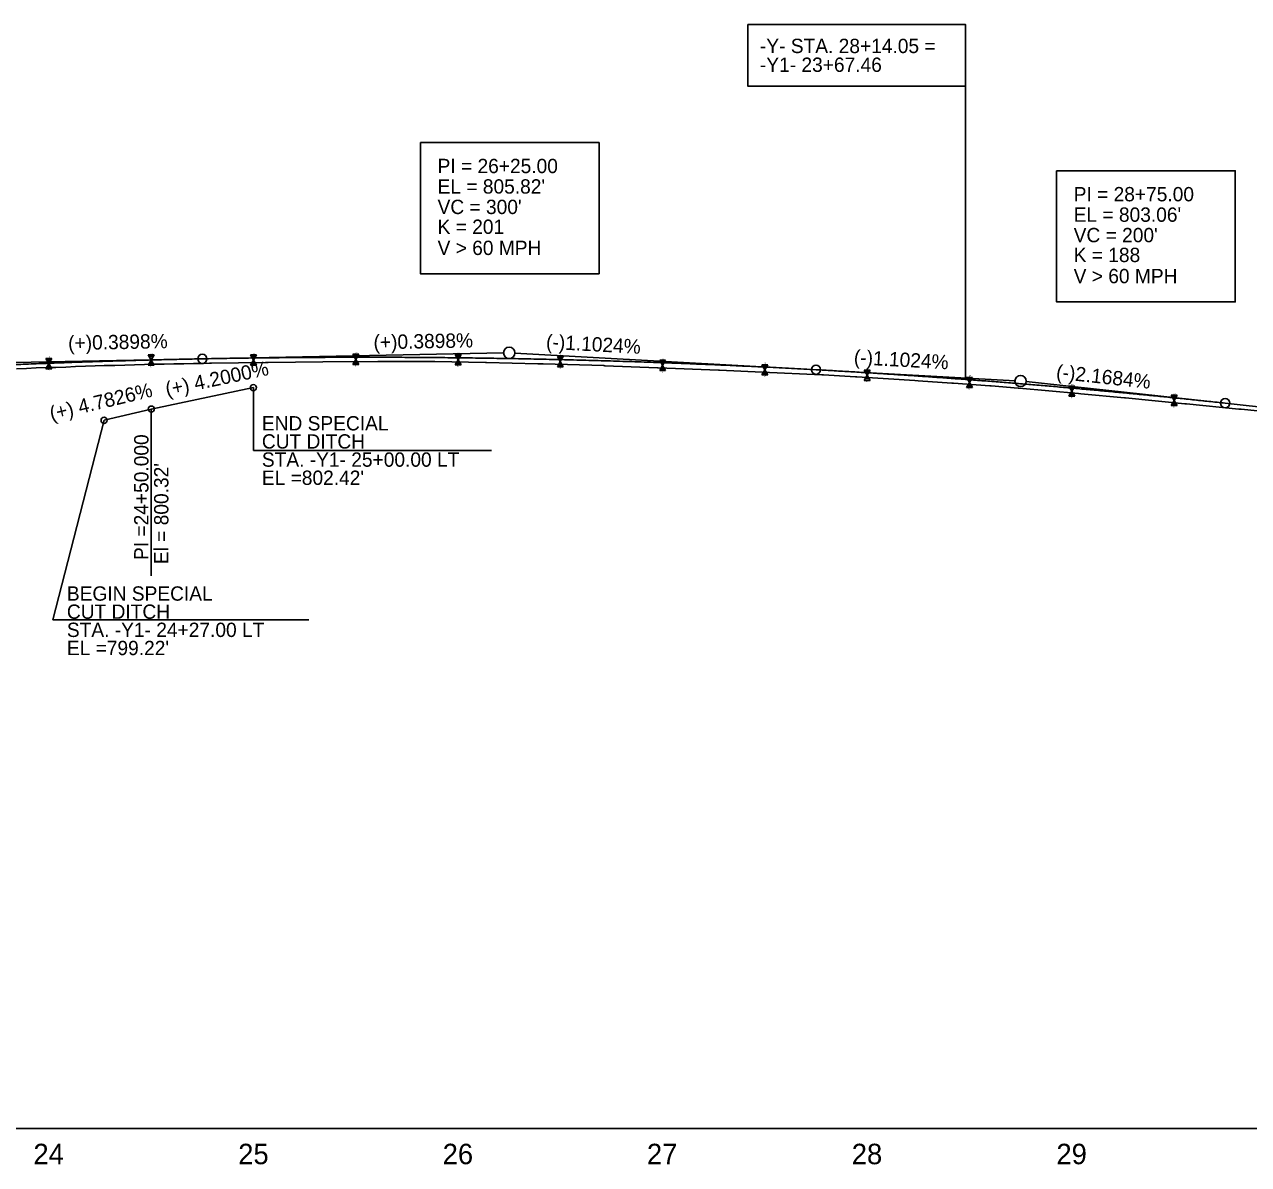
# Model space of a CAD drawing. Extents: x 579185 to 595036, y -53221 to -44640.
# Drawn here: x 580710 to 581308, y -48575 to -48018 of the extents above; entities that cross this region are included whole.
import ezdxf

# ---------------------------------------------------------------- set-up
doc = ezdxf.new("R2010")
doc.units = 0
for name, color, linetype in [('Exist Profile Cell', 7, 'Continuous'), ('Exist Vertical Profile Ground Line', 7, 'Continuous'), ('Exist Vertical Profile Horizontal Axis Label Major', 7, 'Continuous'), ('Old_Level_2', 7, 'Continuous'), ('Prop Grid Mask', 7, 'Continuous'), ('Prop Vertical Profile Curve Label', 7, 'Continuous'), ('Prop Vertical Profile Ditch Grade Left', 7, 'Continuous'), ('Prop Vertical Profile Ditch Grade Left Label', 7, 'Continuous'), ('Prop Vertical Profile Grade', 7, 'Continuous'), ('Prop Vertical Profile Grade Label', 7, 'Continuous'), ('Prop VPI Ditch Grade Left Label', 7, 'Continuous'), ('Prop VPI Label', 7, 'Continuous')]:
    doc.layers.add(name, color=color, linetype=linetype)

msp = doc.modelspace()

# ---------------------------------------------------------------- linework, layer by layer
at = {"layer": 'Exist Profile Cell'}
msp.add_line((579321.48, -48557.09), (581829.78, -48557.09), dxfattribs=at)
at = {"layer": 'Exist Vertical Profile Ground Line'}
msp.add_lwpolyline([(580705.7, -48185.81), (580710.5, -48185.61), (580715.31, -48185.41), (580720.12, -48185.22), (580720.51, -48185.2), (580722.07, -48185.17), (580724.16, -48185.13), (580724.92, -48185.1), (580729.73, -48184.93), (580734.54, -48184.75), (580739.35, -48184.58), (580744.15, -48184.41), (580748.52, -48184.26), (580748.96, -48184.25), (580750.36, -48184.23), (580753.77, -48184.13), (580758.58, -48184), (580763.38, -48183.87), (580768.19, -48183.74), (580773, -48183.61), (580774.2, -48183.57), (580775.56, -48183.55), (580777.8, -48183.51), (580782.61, -48183.42), (580787.42, -48183.33), (580792.23, -48183.24), (580797.03, -48183.15), (580799.93, -48183.1), (580800.89, -48183.08), (580827.28, -48182.75), (580827.95, -48182.75), (580828.6, -48182.74), (580855.37, -48182.48), (580882.3, -48182.16), (580882.67, -48182.16), (580883, -48182.16), (580909.82, -48182.25), (580910.21, -48182.26), (580934.93, -48182.78), (580935.33, -48182.8), (580960.5, -48183.33), (580962.75, -48183.4), (580963.06, -48183.41), (580992.75, -48184.26), (580993.18, -48184.28), (581018.94, -48185.27), (581019.32, -48185.28), (581048.77, -48186.42), (581049.24, -48186.44), (581070.14, -48187.41), (581099.34, -48188.77), (581100.14, -48188.82), (581115.84, -48189.78), (581116.34, -48189.81), (581144.82, -48191.56), (581146.35, -48191.64), (581162.93, -48192.83), (581163.62, -48192.89), (581181.47, -48194.08), (581182.03, -48194.13), (581195.27, -48195.28), (581195.7, -48195.32), (581224.81, -48197.85), (581225.9, -48197.96), (581247.31, -48200.03), (581247.79, -48200.07), (581276.68, -48202.87), (581277.55, -48202.95), (581303.18, -48205.5), (581304.3, -48205.61), (581333.03, -48208.47)], dxfattribs=at)
at = {"layer": 'Old_Level_2'}
for p, q in [((580721.48, -48183.25), (580720.04, -48180.75)), ((580720.04, -48180.75), (580722.93, -48180.75)), ((580720.04, -48185.75), (580721.48, -48183.25)), ((580720.52, -48181.58), (580722.45, -48181.58)), ((580721, -48182.41), (580721.97, -48182.41)), ((580721, -48184.08), (580721.96, -48184.08)), ((580721.48, -48183.25), (580722.93, -48180.75)), ((580722.93, -48185.75), (580721.48, -48183.25)), ((580771.48, -48181.53), (580770.04, -48179.03)), ((580770.04, -48179.03), (580772.93, -48179.03)), ((580770.04, -48184.03), (580771.48, -48181.53)), ((580770.04, -48184.03), (580772.93, -48184.03)), ((580770.52, -48179.86), (580772.45, -48179.86)), ((580770.52, -48183.19), (580772.45, -48183.19)), ((580771, -48180.69), (580771.97, -48180.69)), ((580771, -48182.36), (580771.96, -48182.36)), ((580771.48, -48181.53), (580772.93, -48179.03)), ((580772.93, -48184.03), (580771.48, -48181.53)), ((580821.48, -48181.51), (580820.04, -48179.01)), ((580820.04, -48179.01), (580822.93, -48179.01)), ((580820.04, -48184.01), (580821.48, -48181.51)), ((580820.04, -48184.01), (580822.93, -48184.01)), ((580820.52, -48179.84), (580822.45, -48179.84)), ((580820.52, -48183.18), (580822.45, -48183.18)), ((580821, -48180.68), (580821.97, -48180.68)), ((580821, -48182.35), (580821.96, -48182.35)), ((580821.48, -48181.51), (580822.93, -48179.01)), ((580822.93, -48184.01), (580821.48, -48181.51)), ((580871.48, -48181.2), (580870.04, -48178.7)), ((580870.04, -48178.7), (580872.93, -48178.7)), ((580870.04, -48183.7), (580871.48, -48181.2)), ((580870.04, -48183.7), (580872.93, -48183.7)), ((580870.52, -48179.53), (580872.45, -48179.53)), ((580870.52, -48182.87), (580872.45, -48182.87)), ((580871, -48180.37), (580871.97, -48180.37)), ((580871, -48182.04), (580871.96, -48182.04)), ((580871.48, -48181.2), (580872.93, -48178.7)), ((580872.93, -48183.7), (580871.48, -48181.2)), ((580921.48, -48181.34), (580920.04, -48178.84)), ((580920.04, -48178.84), (580922.93, -48178.84)), ((580920.04, -48183.84), (580921.48, -48181.34)), ((580920.04, -48183.84), (580922.93, -48183.84)), ((580920.52, -48179.67), (580922.45, -48179.67)), ((580920.52, -48183.01), (580922.45, -48183.01)), ((580921, -48180.51), (580921.97, -48180.51)), ((580921, -48182.18), (580921.96, -48182.18)), ((580921.48, -48181.34), (580922.93, -48178.84)), ((580922.93, -48183.84), (580921.48, -48181.34)), ((580971.48, -48182.31), (580970.04, -48179.81)), ((580970.04, -48179.81), (580972.93, -48179.81)), ((580970.04, -48184.81), (580971.48, -48182.31)), ((580970.52, -48180.64), (580972.45, -48180.64)), ((580970.52, -48183.98), (580972.45, -48183.98)), ((580971, -48181.48), (580971.97, -48181.48)), ((580971, -48183.15), (580971.96, -48183.15)), ((580971.48, -48182.31), (580972.93, -48179.81)), ((580972.93, -48184.81), (580971.48, -48182.31)), ((581021.48, -48184.14), (581020.04, -48181.64)), ((581020.04, -48181.64), (581022.93, -48181.64)), ((581020.04, -48186.64), (581021.48, -48184.14)), ((581020.52, -48182.47), (581022.45, -48182.47)), ((581021, -48183.3), (581021.97, -48183.3)), ((581021.48, -48184.14), (581022.93, -48181.64)), ((581022.93, -48186.64), (581021.48, -48184.14)), ((581071.48, -48186.31), (581070.04, -48183.81)), ((581070.04, -48183.81), (581072.93, -48183.81)), ((581071.48, -48186.31), (581072.93, -48183.81)), ((580720.04, -48185.75), (580722.93, -48185.75)), ((580720.52, -48184.91), (580722.45, -48184.91)), ((580970.04, -48184.81), (580972.93, -48184.81)), ((581020.04, -48186.64), (581022.93, -48186.64)), ((581020.52, -48185.8), (581022.45, -48185.8)), ((581021, -48184.97), (581021.96, -48184.97)), ((581070.04, -48188.81), (581071.48, -48186.31)), ((581070.04, -48188.81), (581072.93, -48188.81)), ((581070.52, -48184.64), (581072.45, -48184.64)), ((581070.52, -48187.97), (581072.45, -48187.97)), ((581071, -48185.47), (581071.97, -48185.47)), ((581071, -48187.14), (581071.96, -48187.14)), ((581072.93, -48188.81), (581071.48, -48186.31)), ((581121.48, -48188.95), (581120.04, -48186.45)), ((581120.04, -48186.45), (581122.93, -48186.45)), ((581120.04, -48191.45), (581121.48, -48188.95)), ((581120.52, -48187.28), (581122.45, -48187.28)), ((581121, -48188.11), (581121.97, -48188.11)), ((581121, -48189.78), (581121.96, -48189.78)), ((581121.48, -48188.95), (581122.93, -48186.45)), ((581122.93, -48191.45), (581121.48, -48188.95)), ((581171.48, -48192.48), (581170.04, -48189.98)), ((581170.04, -48189.98), (581172.93, -48189.98)), ((581171.48, -48192.48), (581172.93, -48189.98)), ((581120.04, -48191.45), (581122.93, -48191.45)), ((581120.52, -48190.61), (581122.45, -48190.61)), ((581170.04, -48194.98), (581171.48, -48192.48)), ((581170.04, -48194.98), (581172.93, -48194.98)), ((581170.52, -48190.81), (581172.45, -48190.81)), ((581170.52, -48194.14), (581172.45, -48194.14)), ((581171, -48191.64), (581171.97, -48191.64)), ((581171, -48193.31), (581171.96, -48193.31)), ((581172.93, -48194.98), (581171.48, -48192.48)), ((581221.48, -48196.74), (581220.04, -48194.24)), ((581220.04, -48194.24), (581222.93, -48194.24)), ((581220.52, -48195.07), (581222.45, -48195.07)), ((581221, -48195.9), (581221.97, -48195.9)), ((581221.48, -48196.74), (581222.93, -48194.24)), ((581220.04, -48199.24), (581221.48, -48196.74)), ((581220.04, -48199.24), (581222.93, -48199.24)), ((581220.52, -48198.4), (581222.45, -48198.4)), ((581221, -48197.57), (581221.96, -48197.57)), ((581222.93, -48199.24), (581221.48, -48196.74)), ((581271.48, -48201.25), (581270.04, -48198.75)), ((581270.04, -48198.75), (581272.93, -48198.75)), ((581270.04, -48203.75), (581271.48, -48201.25)), ((581270.52, -48199.58), (581272.45, -48199.58)), ((581271, -48200.42), (581271.97, -48200.42)), ((581271, -48202.09), (581271.96, -48202.09)), ((581271.48, -48201.25), (581272.93, -48198.75)), ((581272.93, -48203.75), (581271.48, -48201.25)), ((581270.04, -48203.75), (581272.93, -48203.75)), ((581270.52, -48202.92), (581272.45, -48202.92))]:
    msp.add_line(p, q, dxfattribs=at)
at = {"layer": 'Prop Grid Mask'}
for points in [[(581063.21, -48017.51), (581169.53, -48017.51), (581169.53, -48047.7), (581063.21, -48047.7)], [(580903.09, -48075.2), (580990.45, -48075.2), (580990.45, -48139.37), (580903.09, -48139.37)], [(581214.03, -48088.98), (581301.39, -48088.98), (581301.39, -48153.15), (581214.03, -48153.15)]]:
    msp.add_lwpolyline(points, close=True, dxfattribs=at)
at = {"layer": 'Prop Vertical Profile Curve Label'}
msp.add_line((581169.53, -48191), (581169.53, -48047.7), dxfattribs=at)
for centre in [(580796.48, -48180.92), (580796.48, -48180.92), (581096.48, -48186.26), (581096.48, -48186.26), (581296.48, -48202.62)]:
    msp.add_circle(centre, 2.25, dxfattribs=at)
at = {"layer": 'Prop Vertical Profile Ditch Grade Left'}
msp.add_lwpolyline([(580748.48, -48210.99), (580771.48, -48205.49), (580821.48, -48194.99)], dxfattribs=at)
at = {"layer": 'Prop Vertical Profile Ditch Grade Left Label'}
for p, q in [((580821.48, -48225.74), (580821.48, -48194.99)), ((580771.48, -48287.05), (580771.48, -48205.49)), ((580723.33, -48308.58), (580748.48, -48210.99)), ((580821.48, -48225.74), (580937.78, -48225.74)), ((580723.33, -48308.58), (580848.52, -48308.58))]:
    msp.add_line(p, q, dxfattribs=at)
for centre in [(580821.48, -48194.99), (580771.48, -48205.49), (580748.48, -48210.99)]:
    msp.add_circle(centre, 1.5, dxfattribs=at)
at = {"layer": 'Prop Vertical Profile Grade'}
msp.add_line((581296.48, -48202.62), (581546.48, -48229.72), dxfattribs=at)
for points in [[(580546.48, -48193.64), (580551.48, -48193.23), (580556.48, -48192.83), (580561.48, -48192.43), (580566.48, -48192.04), (580571.48, -48191.66), (580576.48, -48191.28), (580581.48, -48190.91), (580586.48, -48190.55), (580591.48, -48190.19), (580596.48, -48189.84), (580601.48, -48189.49), (580606.48, -48189.15), (580611.48, -48188.82), (580616.48, -48188.5), (580621.48, -48188.17), (580626.48, -48187.86), (580631.48, -48187.55), (580636.48, -48187.25), (580641.48, -48186.96), (580646.48, -48186.67), (580651.48, -48186.38), (580656.48, -48186.11), (580661.48, -48185.84), (580666.48, -48185.57), (580671.48, -48185.32), (580676.48, -48185.07), (580681.48, -48184.82), (580686.48, -48184.58), (580691.48, -48184.35), (580696.48, -48184.12), (580701.48, -48183.9), (580706.48, -48183.69), (580711.48, -48183.48), (580716.48, -48183.28), (580721.48, -48183.09), (580726.48, -48182.9), (580731.48, -48182.72), (580736.48, -48182.54), (580741.48, -48182.37), (580746.48, -48182.21), (580751.48, -48182.05), (580756.48, -48181.9), (580761.48, -48181.76), (580766.48, -48181.62), (580771.48, -48181.48), (580776.48, -48181.36), (580781.48, -48181.24), (580786.48, -48181.13), (580791.48, -48181.02), (580796.48, -48180.92)], [(580796.48, -48180.92), (580802.48, -48180.81), (580808.48, -48180.7), (580814.48, -48180.61), (580820.48, -48180.52), (580826.48, -48180.45), (580832.48, -48180.38), (580838.48, -48180.32), (580844.48, -48180.27), (580850.48, -48180.23), (580856.48, -48180.2), (580862.48, -48180.17), (580868.48, -48180.16), (580874.48, -48180.16), (580880.48, -48180.16), (580886.48, -48180.17), (580892.48, -48180.19), (580898.48, -48180.22), (580904.48, -48180.26), (580910.48, -48180.31), (580916.48, -48180.37), (580922.48, -48180.44), (580928.48, -48180.51), (580934.48, -48180.6), (580940.48, -48180.69), (580946.48, -48180.79), (580952.48, -48180.9), (580958.48, -48181.03), (580964.48, -48181.15), (580970.48, -48181.29), (580976.48, -48181.44), (580982.48, -48181.6), (580988.48, -48181.76), (580994.48, -48181.94), (581000.48, -48182.12), (581006.48, -48182.31), (581012.48, -48182.51), (581018.48, -48182.72), (581024.48, -48182.94), (581030.48, -48183.17), (581036.48, -48183.4), (581042.48, -48183.65), (581048.48, -48183.9), (581054.48, -48184.17), (581060.48, -48184.44), (581066.48, -48184.72), (581072.48, -48185.01), (581078.48, -48185.31), (581084.48, -48185.62), (581090.48, -48185.94), (581096.48, -48186.26)], [(581096.48, -48186.26), (581100.48, -48186.49), (581104.48, -48186.71), (581108.48, -48186.94), (581112.48, -48187.18), (581116.48, -48187.42), (581120.48, -48187.66), (581124.48, -48187.91), (581128.48, -48188.16), (581132.48, -48188.42), (581136.48, -48188.68), (581140.48, -48188.95), (581144.48, -48189.22), (581148.48, -48189.49), (581152.48, -48189.77), (581156.48, -48190.05), (581160.48, -48190.34), (581164.48, -48190.63), (581168.48, -48190.92), (581172.48, -48191.22), (581176.48, -48191.53), (581180.48, -48191.83), (581184.48, -48192.15), (581188.48, -48192.46), (581192.48, -48192.78), (581196.48, -48193.11), (581200.48, -48193.44), (581204.48, -48193.77), (581208.48, -48194.11), (581212.48, -48194.45), (581216.48, -48194.8), (581220.48, -48195.15), (581224.48, -48195.5), (581228.48, -48195.86), (581232.48, -48196.22), (581236.48, -48196.59), (581240.48, -48196.96), (581244.48, -48197.34), (581248.48, -48197.72), (581252.48, -48198.11), (581256.48, -48198.49), (581260.48, -48198.89), (581264.48, -48199.28), (581268.48, -48199.69), (581272.48, -48200.09), (581276.48, -48200.5), (581280.48, -48200.92), (581284.48, -48201.34), (581288.48, -48201.76), (581292.48, -48202.19), (581296.48, -48202.62)]]:
    msp.add_spline(points, degree=3, dxfattribs=at)
at = {"layer": 'Prop VPI Label'}
for p, q in [((580796.48, -48180.92), (580943.73, -48178.05)), ((581096.48, -48186.26), (580949.23, -48178.15)), ((580796.48, -48180.92), (580674.23, -48183.3)), ((581096.48, -48186.26), (581193.74, -48191.62)), ((581296.48, -48202.62), (581199.22, -48192.07))]:
    msp.add_line(p, q, dxfattribs=at)
for centre in [(580946.48, -48178), (581196.48, -48191.78)]:
    msp.add_circle(centre, 2.75, dxfattribs=at)

# ---------------------------------------------------------------- texts
at = {"layer": 'Exist Vertical Profile Horizontal Axis Label Major'}
for s, p in [('24', (580713.93, -48574.59)), ('25', (580814.03, -48574.59)), ('26', (580913.97, -48574.59)), ('27', (581013.82, -48574.59)), ('28', (581113.95, -48574.59)), ('29', (581213.99, -48574.59))]:
    msp.add_text(s, height=10, dxfattribs=at).set_placement(p)
at = {"layer": 'Old_Level_2'}
for p in [(580771.25, -48178.87), (580821.25, -48178.85), (580871.25, -48178.54), (580921.25, -48178.68), (580721.25, -48180.59), (580771.06, -48185.03), (580821.06, -48185.02), (580871.06, -48184.71), (580921.06, -48184.85), (580971.25, -48179.65), (581021.25, -48181.48), (581071.25, -48183.65), (580721.06, -48186.75), (580971.06, -48185.82), (581021.06, -48187.64), (581071.06, -48189.81), (581121.25, -48186.29), (581171.25, -48189.82), (581121.06, -48192.45), (581171.06, -48195.98), (581221.25, -48194.08), (581221.06, -48200.24), (581271.25, -48198.59), (581271.06, -48204.76)]:
    msp.add_text('6"', height=0.8, dxfattribs=at).set_placement(p)
at = {"layer": 'Prop Vertical Profile Curve Label'}
for s, p in [("VC = 300'", (580911.48, -48110.17)), ('K = 201', (580911.48, -48119.86)), ("VC = 200'", (581222.42, -48123.95)), ('V > 60 MPH', (580911.48, -48130.19)), ('K = 188', (581222.42, -48133.64)), ('V > 60 MPH', (581222.42, -48143.97))]:
    msp.add_text(s, height=7, dxfattribs=at).set_placement(p)
at = {"layer": 'Prop Vertical Profile Ditch Grade Left Label'}
for s, rotation, p in [('(+) 4.2000%', 11.85978, (580779.23, -48199.3)), ('(+) 4.7826%', 13.44862, (580722.78, -48211.21))]:
    msp.add_text(s, height=7, rotation=rotation, dxfattribs=at).set_placement(p)
for s, p in [('END SPECIAL', (580825.59, -48215.93)), ('CUT DITCH', (580825.59, -48224.8)), ('STA. -Y1- 25+00.00 LT ', (580825.59, -48233.67)), ("EL =802.42'", (580825.59, -48242.55)), ('BEGIN SPECIAL', (580730.27, -48299.14)), ('CUT DITCH', (580730.27, -48308.01)), ('STA. -Y1- 24+27.00 LT ', (580730.27, -48316.89)), ("EL =799.22'", (580730.27, -48325.76))]:
    msp.add_text(s, height=7, dxfattribs=at).set_placement(p)
at = {"layer": 'Prop Vertical Profile Grade Label'}
for s, rotation, p in [('(+)0.3898%', 1.11661, (580730.95, -48176.67)), ('(+)0.3898%', 1.11661, (580880.22, -48176.29)), ('(-)1.1024%', 356.84505, (580964.37, -48175.98)), ('(-)1.1024%', 356.84505, (581114.84, -48183.53)), ('(-)2.1684%', 353.8121, (581213.62, -48190.62))]:
    msp.add_text(s, height=7, rotation=rotation, dxfattribs=at).set_placement(p)
at = {"layer": 'Prop VPI Ditch Grade Left Label'}
for s, p in [('PI =24+50.000', (580770.15, -48279.26)), ("El = 800.32'", (580779.9, -48281.29))]:
    msp.add_text(s, height=7, rotation=90, dxfattribs=at).set_placement(p)
at = {"layer": 'Prop VPI Label'}
for s, p in [('-Y- STA. 28+14.05 =', (581069.06, -48031.49)), ('-Y1- 23+67.46', (581069.06, -48040.67)), ('PI = 26+25.00', (580911.48, -48090.17)), ("EL = 805.82'", (580911.48, -48100.17)), ('PI = 28+75.00', (581222.42, -48103.95)), ("EL = 803.06'", (581222.42, -48113.95))]:
    msp.add_text(s, height=7, dxfattribs=at).set_placement(p)

doc.saveas('drawing.dxf')
